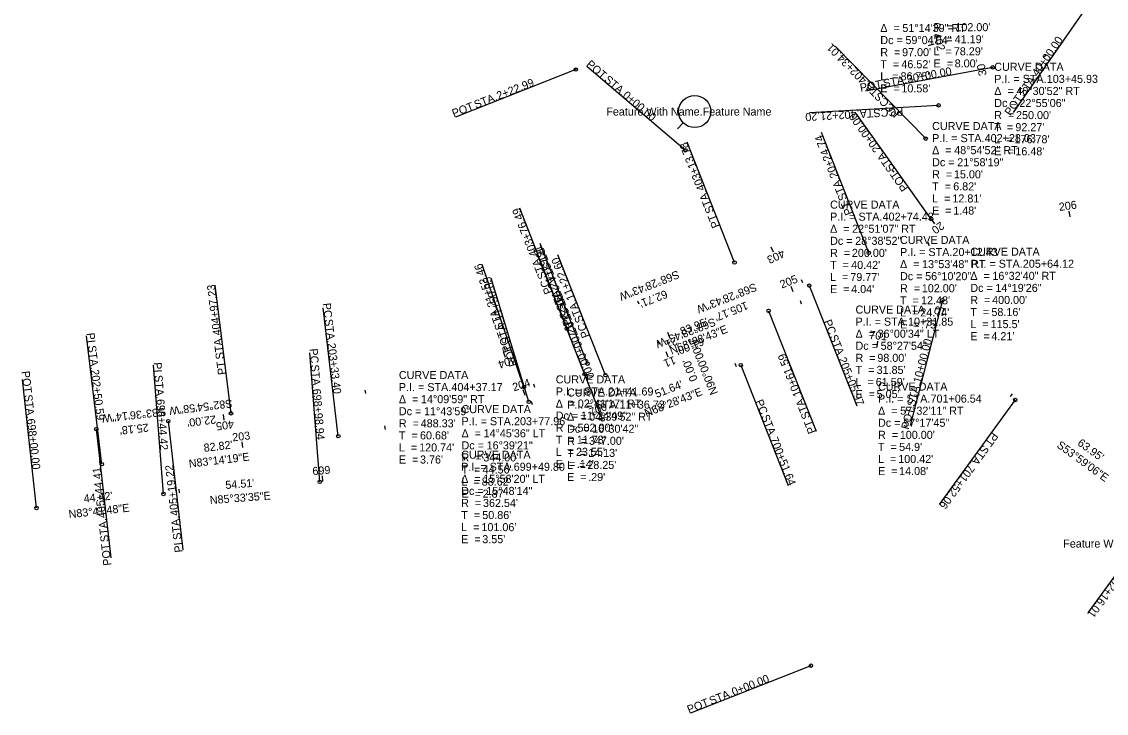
# Model space of a CAD drawing. Extents: x 1600023 to 1602131, y 285824 to 287284.
# Drawn here: x 1600627.4 to 1601004.6, y 286516.7 to 286757.4 of the extents above; entities that cross this region are included whole.
import ezdxf

# ---------------------------------------------------------------- set-up
doc = ezdxf.new("R2010")
doc.units = 0
for name, color, linetype in [('_CIVIL_CONSTRUCTION', 7, 'Continuous'), ('Default', 7, 'Continuous'), ('GE_P_Alignment', 7, 'Continuous'), ('PF_P_Grade_Line', 7, 'Continuous'), ('PF_X_Ground_Line', 7, 'Continuous'), ('PV_P_Curb', 7, 'Continuous'), ('SC_Scratch6', 7, 'Continuous'), ('SC_Scratch8', 7, 'Continuous')]:
    doc.layers.add(name, color=color, linetype=linetype)

msp = doc.modelspace()

# ---------------------------------------------------------------- linework, layer by layer
at = {"layer": '_CIVIL_CONSTRUCTION'}
for p, q in [((1600820.1, 286740.73), (1600778.24, 286724.22)), ((1600858.21, 286712.63), (1600823.92, 286741.77)), ((1600823.21, 286634.77), (1600806.71, 286676.63)), ((1600901.31, 286665.57), (1600917.82, 286623.7)), ((1600737.52, 286613.18), (1600732.22, 286657.87)), ((1600655.28, 286603.43), (1600649.98, 286648.12)), ((1600901.9, 286533.29), (1600860.04, 286516.78))]:
    msp.add_line(p, q, dxfattribs=at)
for centre in [(1600820.1, 286740.73), (1600858.21, 286712.63), (1600901.31, 286665.57), (1600823.21, 286634.77), (1600737.52, 286613.18), (1600655.28, 286603.43), (1600901.9, 286533.29)]:
    msp.add_circle(centre, 0.6, dxfattribs=at)
at = {"layer": 'Default'}
for p, q in [((1600997.93, 286762.76), (1600972.29, 286725.78)), ((1600941.81, 286716.69), (1600910.34, 286748.85)), ((1600942.79, 286749.14), (1600944.71, 286749.68)), ((1600965.11, 286741.49), (1600920.87, 286733.24)), ((1600965.11, 286741.49), (1600963.14, 286741.12)), ((1600946.3, 286728.27), (1600901.37, 286725.69)), ((1600943.72, 286688.73), (1600917.64, 286725.4)), ((1600922.03, 286676.96), (1600905.52, 286718.82)), ((1600875.32, 286673.59), (1600858.81, 286715.45)), ((1600929.95, 286705.97), (1600930.72, 286705.05)), ((1600816.98, 286650.58), (1600800.67, 286692.52)), ((1600943.72, 286688.73), (1600944.88, 286687.1)), ((1600824.19, 286638.38), (1600807.68, 286680.24)), ((1600887.95, 286679.08), (1600888.81, 286677.28)), ((1600802.08, 286630.26), (1600787.56, 286672.85)), ((1600830.42, 286634.39), (1600813.91, 286676.25)), ((1600700.21, 286621.1), (1600694.66, 286665.76)), ((1600803.75, 286625.1), (1600790.7, 286668.17)), ((1600898.53, 286667.69), (1600898.97, 286666.58)), ((1600829.45, 286618.95), (1600812.94, 286660.82)), ((1600841.62, 286660.3), (1600842.06, 286659.19)), ((1600898.18, 286660.37), (1600898.49, 286659.21)), ((1600947.64, 286660.48), (1600936.38, 286616.91)), ((1600947.64, 286660.48), (1600947.14, 286658.55)), ((1600887.17, 286656.77), (1600903.68, 286614.9)), ((1600852.02, 286649.35), (1600852.75, 286647.49)), ((1600924.95, 286644.29), (1600925.17, 286646.27)), ((1600794.87, 286642.59), (1600795.5, 286640.7)), ((1600851.44, 286642.68), (1600852.18, 286640.82)), ((1600731.07, 286597.28), (1600727.59, 286642.14)), ((1600676.73, 286593.06), (1600673.24, 286637.92)), ((1600875.97, 286637.3), (1600875.52, 286638.41)), ((1600877.49, 286637.9), (1600893.99, 286596.03)), ((1600632.57, 286588.18), (1600627.63, 286632.91)), ((1600805.36, 286631.39), (1600805.75, 286630.25)), ((1600746.72, 286629.19), (1600746.98, 286628.01)), ((1600971.3, 286626.95), (1600971.98, 286627.93)), ((1600804.56, 286625.35), (1600804.91, 286624.2)), ((1600972.97, 286625.76), (1600946.51, 286589.36)), ((1600697.46, 286620.76), (1600697.7, 286618.78)), ((1600829.45, 286618.95), (1600828.72, 286620.82)), ((1600678.38, 286618.39), (1600683.4, 286573.67)), ((1600653.36, 286615.59), (1600658.37, 286570.87)), ((1600781.54, 286604.8), (1600781.28, 286605.97)), ((1600732.13, 286597.36), (1600731.97, 286599.36)), ((1600682.28, 286593.49), (1600682.19, 286594.69)), ((1601024.7, 286588.15), (1600998.24, 286551.75))]:
    msp.add_line(p, q, dxfattribs=at)
for centre in [(1600965.11, 286741.49), (1600946.3, 286728.27), (1600941.81, 286716.69), (1600943.72, 286688.73), (1600922.03, 286676.96), (1600875.32, 286673.59), (1600947.64, 286660.48), (1600887.17, 286656.77), (1600816.98, 286650.58), (1600824.19, 286638.38), (1600830.42, 286634.39), (1600877.49, 286637.9), (1600802.08, 286630.26), (1600803.75, 286625.1), (1600972.97, 286625.76), (1600700.21, 286621.1), (1600653.36, 286615.59), (1600678.38, 286618.39), (1600829.45, 286618.95), (1600731.07, 286597.28), (1600676.73, 286593.06), (1600632.57, 286588.18)]:
    msp.add_circle(centre, 0.6, dxfattribs=at)
at = {"layer": 'PV_P_Curb'}
msp.add_circle((1600861.48, 286726.12), 5.6, dxfattribs=at)
at = {"layer": 'SC_Scratch6'}
for p, q in [((1600982.8, 286745.17), (1600983.82, 286745.81)), ((1600992.02, 286689.51), (1600991.74, 286691.49)), ((1600943.08, 286679.43), (1600942.76, 286680.59)), ((1600895.76, 286663.38), (1600895.03, 286665.24)), ((1600849.25, 286645.03), (1600848.8, 286646.15)), ((1600802.49, 286627.35), (1600801.87, 286629.26)), ((1600753.95, 286615.53), (1600753.75, 286616.71)), ((1600704.35, 286609.25), (1600704.12, 286611.23)), ((1600654.7, 286603.36), (1600654.57, 286604.56))]:
    msp.add_line(p, q, dxfattribs=at)
at = {"layer": 'SC_Scratch8'}
msp.add_line((1600855.48, 286720.12), (1600857.52, 286722.16), dxfattribs=at)
msp.add_lwpolyline([(1600855.48, 286720.12), (1600856.19, 286720.83), (1600856.19, 286720.83)], close=True, dxfattribs=at)

# ---------------------------------------------------------------- texts
at = {"layer": '_CIVIL_CONSTRUCTION'}
for s, rotation, p in [('POT', 319.6453, (1600823.51, 286742.17)), ('2+22.99', 21.5214, (1600793.22, 286730.17)), (' STA. ', 319.6453, (1600829, 286737.51)), ('0+00.00', 319.6453, (1600836.2, 286731.39)), ('POT', 21.5214, (1600777.72, 286724.07)), (' STA. ', 21.5214, (1600784.42, 286726.71)), ('PT', 291.5214, (1600806.25, 286677.89)), (' STA. ', 291.5214, (1600807.87, 286673.79)), ('204+22.02', 291.5214, (1600811.34, 286664.99)), ('PC', 276.7614, (1600732.09, 286659.35)), (' STA. ', 276.7614, (1600732.63, 286654.8)), ('PC', 291.5214, (1600906.28, 286653.08)), ('PI', 276.7614, (1600649.92, 286648.98)), (' STA. ', 291.5214, (1600907.96, 286648.81)), (' STA. ', 276.7614, (1600650.32, 286645.61)), ('203+33.40', 276.7614, (1600733.74, 286645.41)), ('205+05.97', 291.5214, (1600911.43, 286640.02)), ('202+50.59', 276.7614, (1600651.43, 286636.23)), ('0+00.00', 21.5214, (1600874.99, 286522.73)), ('POT', 21.5214, (1600859.5, 286516.62)), (' STA. ', 21.5214, (1600866.2, 286519.26))]:
    msp.add_text(s, height=2.8, rotation=rotation, dxfattribs=at).set_placement(p)
at = {"layer": 'Default'}
for s, p in [('Δ  = ', (1600926.02, 286753.79)), ('51°14\'39" RT', (1600933.7, 286753.79)), ('R  = ', (1600944.56, 286754.08)), ("102.00'", (1600952.14, 286754.08)), ('Dc = ', (1600926.02, 286749.59)), ('59°04\'04"', (1600934.76, 286749.59)), ('T  = ', (1600944.56, 286749.88)), ("41.19'", (1600951.9, 286749.88)), ('R  = ', (1600926.02, 286745.39)), ("97.00'", (1600933.6, 286745.39)), ('L  = ', (1600944.56, 286745.68)), ("78.29'", (1600951.6, 286745.68)), ('E  = ', (1600944.56, 286741.48)), ("8.00'", (1600951.9, 286741.48)), ('T  = ', (1600926.02, 286741.19)), ("46.52'", (1600933.36, 286741.19)), ('L  = ', (1600926.02, 286736.99)), ("86.75'", (1600933.06, 286736.99)), ('E  = ', (1600926.02, 286732.79)), ("10.58'", (1600933.36, 286732.79)), ('CURVE DATA', (1600944.05, 286719.68)), ('P.I. = STA. ', (1600944.05, 286715.48)), ('402+28.03', (1600962.32, 286715.48)), ('48°54\'52" RT', (1600951.73, 286711.28)), ('Δ  = ', (1600944.05, 286711.28)), ('Dc = ', (1600944.05, 286707.08)), ('21°58\'19"', (1600952.79, 286707.08)), ('R  = ', (1600944.05, 286702.88)), ("15.00'", (1600951.64, 286702.88)), ('T  = ', (1600944.05, 286698.68)), ("6.82'", (1600951.39, 286698.68)), ('L  = ', (1600944.05, 286694.48)), ("12.81'", (1600951.1, 286694.48)), ('CURVE DATA', (1600908.56, 286692.34)), ('E  = ', (1600944.05, 286690.28)), ("1.48'", (1600951.39, 286690.28)), ('P.I. = STA. ', (1600908.56, 286688.14)), ('402+74.43', (1600926.83, 286688.14)), ('Δ  = ', (1600908.56, 286683.94)), ('22°51\'07" RT', (1600916.24, 286683.94)), ('Dc = ', (1600908.56, 286679.74)), ('28°38\'52"', (1600917.3, 286679.74)), ('CURVE DATA', (1600932.88, 286680.04)), ('R  = ', (1600908.56, 286675.54)), ("200.00'", (1600916.15, 286675.54)), ('P.I. = STA. ', (1600932.88, 286675.84)), ('20+12.43', (1600951.14, 286675.84)), ('T  = ', (1600908.56, 286671.34)), ("40.42'", (1600915.9, 286671.34)), ('Δ  = ', (1600932.88, 286671.64)), ('13°53\'48" RT', (1600940.55, 286671.64)), ('L  = ', (1600908.56, 286667.14)), ("79.77'", (1600915.6, 286667.14)), ('Dc = ', (1600932.88, 286667.44)), ('56°10\'20"', (1600941.62, 286667.44)), ('E  = ', (1600908.56, 286662.94)), ("4.04'", (1600915.9, 286662.94)), ('R  = ', (1600932.88, 286663.24)), ("102.00'", (1600940.46, 286663.24)), ('T  = ', (1600932.88, 286659.04)), ("12.43'", (1600940.21, 286659.04)), ('CURVE DATA', (1600917.41, 286655.82)), ('L  = ', (1600932.88, 286654.84)), ("24.74'", (1600939.92, 286654.84)), ('P.I. = STA. ', (1600917.41, 286651.62)), ('10+31.85', (1600935.67, 286651.62)), ('Δ  = ', (1600917.41, 286647.42)), ('36°00\'34" LT', (1600925.08, 286647.42)), ('E  = ', (1600932.88, 286650.64)), (".75'", (1600940.22, 286650.64)), ('Dc = ', (1600917.41, 286643.22)), ('58°27\'54"', (1600926.15, 286643.22)), ('R  = ', (1600917.41, 286639.02)), ("98.00'", (1600924.99, 286639.02)), ('CURVE DATA', (1600758.59, 286633.04)), ('T  = ', (1600917.41, 286634.82)), ("31.85'", (1600924.75, 286634.82)), ('P.I. = STA. ', (1600758.59, 286628.84)), ('404+37.17', (1600776.86, 286628.84)), ('CURVE DATA', (1600813.14, 286631.52)), ('L  = ', (1600917.41, 286630.62)), ("61.59'", (1600924.45, 286630.62)), ('CURVE DATA', (1600925.23, 286629.03)), ('Δ  = ', (1600758.59, 286624.64)), ('14°09\'59" RT', (1600766.27, 286624.64)), ('P.I. = STA. ', (1600813.14, 286627.32)), ('CURVE DATA', (1600817.09, 286626.95)), ('21+41.69', (1600831.4, 286627.32)), ('E  = ', (1600917.41, 286626.42)), ("5.05'", (1600924.75, 286626.42)), ('P.I. = STA. ', (1600925.23, 286624.83)), ('701+06.54', (1600943.5, 286624.83)), ('Δ  = ', (1600813.14, 286623.12)), ('P.I. = STA. ', (1600817.09, 286622.75)), ('02°41\'17" RT', (1600820.81, 286623.12)), ('11+36.73', (1600835.35, 286622.75)), ('Dc = ', (1600758.59, 286620.44)), ('11°43\'59"', (1600767.33, 286620.44)), ('Dc = ', (1600813.14, 286618.92)), ('Δ  = ', (1600817.09, 286618.55)), ('11°24\'49"', (1600821.88, 286618.92)), ('04°39\'52" RT', (1600824.76, 286618.55)), ('Δ  = ', (1600925.23, 286620.63)), ('57°32\'11" RT', (1600932.91, 286620.63)), ('R  = ', (1600758.59, 286616.24)), ("488.33'", (1600766.18, 286616.24)), ('R  = ', (1600813.14, 286614.72)), ('Dc = ', (1600817.09, 286614.35)), ("502.00'", (1600820.72, 286614.72)), ('16°30\'42"', (1600825.82, 286614.35)), ('Dc = ', (1600925.23, 286616.43)), ('57°17\'45"', (1600933.97, 286616.43)), ('T  = ', (1600758.59, 286612.04)), ("60.68'", (1600765.93, 286612.04)), ('T  = ', (1600813.14, 286610.52)), ('R  = ', (1600817.09, 286610.15)), ("11.78'", (1600820.47, 286610.52)), ("347.00'", (1600824.67, 286610.15)), ('R  = ', (1600925.23, 286612.23)), ("100.00'", (1600932.81, 286612.23)), ('L  = ', (1600758.59, 286607.84)), ("120.74'", (1600765.64, 286607.84)), ('L  = ', (1600813.14, 286606.32)), ('T  = ', (1600817.09, 286605.95)), ("23.55'", (1600820.18, 286606.32)), ("14.13'", (1600824.42, 286605.95)), ('T  = ', (1600925.23, 286608.03)), ("54.9'", (1600932.57, 286608.03)), ('E  = ', (1600758.59, 286603.64)), ("3.76'", (1600765.94, 286603.64)), ('CURVE DATA', (1600780.26, 286605.32)), ('E  = ', (1600813.14, 286602.12)), (".14'", (1600820.48, 286602.12)), ('L  = ', (1600925.23, 286603.83)), ("100.42'", (1600932.27, 286603.83)), ('P.I. = STA. ', (1600780.26, 286601.12)), ('699+49.80', (1600798.53, 286601.12)), ('L  = ', (1600817.09, 286601.75)), ("28.25'", (1600824.13, 286601.75)), ('E  = ', (1600925.23, 286599.63)), ("14.08'", (1600932.57, 286599.63)), ('Δ  = ', (1600780.26, 286596.92)), ('15°58\'20" LT', (1600787.94, 286596.92)), ('E  = ', (1600817.09, 286597.55)), (".29'", (1600824.43, 286597.55)), ('Dc = ', (1600780.26, 286592.72)), ('15°48\'14"', (1600789, 286592.72)), ('R  = ', (1600780.26, 286588.52)), ("362.54'", (1600787.84, 286588.52)), ('T  = ', (1600780.26, 286584.32)), ("50.86'", (1600787.6, 286584.32)), ('L  = ', (1600780.26, 286580.12)), ("101.06'", (1600787.3, 286580.12)), ('E  = ', (1600780.26, 286575.92)), ("3.55'", (1600787.6, 286575.92))]:
    msp.add_text(s, height=2.8, dxfattribs=at).set_placement(p)
for s, rotation, p in [('402', 285.8126, (1600944.3, 286752.97)), ('40+00.00', 55.2657, (1600980.79, 286738.11)), ('402+34.01', 134.3733, (1600921.57, 286737.31)), ('30+00.00', 10.5564, (1600935.58, 286736.03)), ('30', 100.5564, (1600963.06, 286738.84)), ('POT', 10.5564, (1600919.21, 286732.98)), (' STA. ', 134.3733, (1600928.18, 286730.55)), (' STA. ', 10.5564, (1600926.29, 286734.3)), (' STA. ', 55.2657, (1600975.4, 286730.34)), ('PCC', 134.3733, (1600933, 286725.63)), ('POT', 55.2657, (1600971.3, 286724.42)), ('402+21.20', 183.2876, (1600917.65, 286726.58)), ('20+00.00', 125.418, (1600926.32, 286713.13)), (' STA. ', 183.2876, (1600927.08, 286727.12)), ('PCC', 183.2876, (1600933.96, 286727.52)), ('20+24.74', 111.5214, (1600911.48, 286703.6)), ('403+13.78', 111.5214, (1600865.2, 286699.13)), (' STA. ', 125.418, (1600931.8, 286705.42)), (' STA. ', 111.5214, (1600914.95, 286694.81)), ('POT', 125.418, (1600935.97, 286699.55)), (' STA. ', 111.5214, (1600868.67, 286690.34)), ('403+76.49', 111.2524, (1600806.94, 286676.27)), ('PT', 111.5214, (1600916.57, 286690.7)), ('PT', 111.5214, (1600870.28, 286686.23)), ('20', 215.418, (1600946.99, 286687.98)), ('21+29.91', 111.5214, (1600813.56, 286665.21)), ('403', 205.4686, (1600891.98, 286678.23)), ('21+53.46', 108.8333, (1600792.37, 286658.6)), (' STA. ', 111.2524, (1600810.37, 286667.46)), ('11+22.60', 111.5214, (1600819.87, 286661.04)), ('S68°28\'43"W', 201.5214, (1600855.45, 286670.91)), ('404+97.23', 97.0838, (1600696.77, 286648.42)), ('11+50.85', 106.8568, (1600795.01, 286653.82)), ('PC', 111.2524, (1600812.03, 286663.19)), ('S68°28\'43"W', 201.5214, (1600882.41, 286666.5)), (' STA. ', 111.5214, (1600817.03, 286656.42)), ('PT', 291.5214, (1600812.47, 286662.14)), ("62.71'", 201.5214, (1600851.34, 286664.09)), (' STA. ', 108.8333, (1600795.42, 286649.65)), (' STA. ', 291.5214, (1600814.09, 286658.03)), (' STA. ', 111.5214, (1600823.34, 286652.24)), ("105.17'", 201.5214, (1600879.34, 286660.08)), ('10', 165.5121, (1600949.18, 286657.5)), ('PC', 111.5214, (1600818.71, 286652.15)), ('S68°28\'43"W', 201.5214, (1600868.1, 286654.4)), (' STA. ', 106.8568, (1600797.75, 286644.77)), ('700+00.00', 291.5214, (1600817.55, 286649.24)), ('PC', 111.5214, (1600825.02, 286647.98)), (' STA. ', 97.0838, (1600697.94, 286639.04)), ('POT', 108.8333, (1600797.75, 286642.84)), ('21', 201.5214, (1600854.82, 286647.77)), ("61.00'", 201.5214, (1600863.99, 286647.58)), ('701', 353.8105, (1600922.09, 286647.11)), ('10+00.00', 75.5121, (1600940.09, 286631.42)), ('PC', 274.4402, (1600727.52, 286643.56)), ('POT', 106.8568, (1600799.83, 286637.88)), ('PI', 274.4402, (1600673.22, 286638.75)), ('PT', 97.0838, (1600698.48, 286634.66)), ('404', 198.4937, (1600798.76, 286641.26)), ('11', 201.5214, (1600854.25, 286641.1)), ('10+61.59', 111.5214, (1600898.65, 286627.55)), ('POT', 276.3033, (1600627.37, 286635.7)), (' STA. ', 274.4402, (1600727.88, 286638.99)), (' STA. ', 274.4402, (1600673.48, 286635.37)), ("51.64'", 21.5214, (1600848.28, 286626.42)), (' STA. ', 75.5121, (1600937.72, 286622.27)), (' STA. ', 276.3033, (1600628.16, 286628.54)), ('698+98.94', 274.4402, (1600728.61, 286629.56)), ('N68°28\'43"E', 21.5214, (1600844.66, 286619.79)), ('698+44.42', 274.4402, (1600674.21, 286625.95)), ('S82°54\'58"W', 187.0838, (1600700.5, 286625.98)), ('700', 21.5214, (1600825.42, 286620.05)), ('PC', 291.5214, (1600882.51, 286625.28)), (' STA. ', 111.5214, (1600902.12, 286618.75)), ('S83°36\'14"W', 186.3962, (1600677.15, 286623.08)), ("22.00'", 187.0838, (1600694.82, 286620.39)), (' STA. ', 291.5214, (1600884.19, 286621.01)), ('POT', 75.5121, (1600935.92, 286615.3)), ('698+00.00', 276.3033, (1600629.2, 286619.14)), ("25.18'", 186.3962, (1600671.4, 286617.57)), ('405', 187.0838, (1600701.05, 286618.69)), ('PT', 111.5214, (1600903.74, 286614.65)), ('700+51.64', 291.5214, (1600887.66, 286612.22)), ('PT', 233.985, (1600965.02, 286614.74)), (' STA. ', 233.985, (1600962.42, 286611.17)), ('S53°59\'06"E', 323.985, (1600987.16, 286609.5)), ("63.95'", 323.985, (1600994.36, 286610.26)), ('405+44.41', 96.3962, (1600656.76, 286584.82)), ('405+19.22', 96.3962, (1600682.02, 286585.61)), ('699', 4.6084, (1600728.63, 286599.59)), ('701+52.06', 233.985, (1600956.87, 286603.53)), ("54.51'", 4.4402, (1600698.35, 286594.78)), ("44.42'", 6.3033, (1600649.12, 286590.03)), ('N85°33\'35"E', 4.4402, (1600692.94, 286589.5)), ('N83°41\'48"E', 6.3033, (1600643.88, 286584.6)), (' STA. ', 96.3962, (1600657.82, 286575.43)), (' STA. ', 96.3962, (1600683.07, 286576.22)), ('POT', 96.3962, (1600658.62, 286568.27)), ('PI', 96.3962, (1600683.45, 286572.85)), ('702+16.01', 233.985, (1601008.42, 286565.69))]:
    msp.add_text(s, height=2.8, rotation=rotation, dxfattribs=at).set_placement(p)
at = {"layer": 'GE_P_Alignment'}
for s, rotation, p in [('N68°28\'43"E', 21.5214, (1600853.45, 286641.53)), ('N90°00\'00"E', 111.5214, (1600869.64, 286628.2)), ('N83°14\'19"E', 6.7614, (1600685.68, 286602.2))]:
    msp.add_text(s, height=2.8, rotation=rotation, dxfattribs=at).set_placement(p)
at = {"layer": 'PF_P_Grade_Line'}
for s, rotation, p in [("83.95'", 21.5214, (1600857.07, 286648.17)), ("0.00'", 111.5214, (1600862.59, 286632.86)), ("82.82'", 6.7614, (1600690.87, 286607.69))]:
    msp.add_text(s, height=2.8, rotation=rotation, dxfattribs=at).set_placement(p)
at = {"layer": 'PF_X_Ground_Line'}
for s, p in [('CURVE DATA', (1600965.66, 286740.29)), ('P.I. = STA. ', (1600965.66, 286736.09)), ('103+45.93', (1600983.93, 286736.09)), ('Δ  = ', (1600965.66, 286731.89)), ('40°30\'52" RT', (1600973.34, 286731.89)), ('Dc = ', (1600965.66, 286727.69)), ('22°55\'06"', (1600974.4, 286727.69)), ('R  = ', (1600965.66, 286723.49)), ("250.00'", (1600973.24, 286723.49)), ('T  = ', (1600965.66, 286719.29)), ("92.27'", (1600973, 286719.29)), ('L  = ', (1600965.66, 286715.09)), ("176.78'", (1600972.7, 286715.09)), ('E  = ', (1600965.66, 286710.89)), ("16.48'", (1600973, 286710.89)), ('CURVE DATA', (1600957.33, 286675.96)), ('P.I. = STA. ', (1600957.33, 286671.76)), ('205+64.12', (1600975.6, 286671.76)), ('Δ  = ', (1600957.33, 286667.56)), ('16°32\'40" RT', (1600965.01, 286667.56)), ('Dc = ', (1600957.33, 286663.36)), ('14°19\'26"', (1600966.07, 286663.36)), ('R  = ', (1600957.33, 286659.16)), ("400.00'", (1600964.91, 286659.16)), ('T  = ', (1600957.33, 286654.96)), ("58.16'", (1600964.67, 286654.96)), ('L  = ', (1600957.33, 286650.76)), ("115.5'", (1600964.37, 286650.76)), ('E  = ', (1600957.33, 286646.56)), ("4.21'", (1600964.67, 286646.56)), ('CURVE DATA', (1600780.37, 286621.17)), ('P.I. = STA. ', (1600780.37, 286616.97)), ('203+77.96', (1600798.63, 286616.97)), ('Δ  = ', (1600780.37, 286612.77)), ('14°45\'36" LT', (1600788.04, 286612.77)), ('Dc = ', (1600780.37, 286608.57)), ('16°39\'21"', (1600789.11, 286608.57)), ('R  = ', (1600780.37, 286604.37)), ("344.00'", (1600787.95, 286604.37)), ('T  = ', (1600780.37, 286600.17)), ("44.56'", (1600787.7, 286600.17)), ('L  = ', (1600780.37, 286595.97)), ("88.62'", (1600787.41, 286595.97)), ('E  = ', (1600780.37, 286591.77)), ("2.87'", (1600787.71, 286591.77))]:
    msp.add_text(s, height=2.8, dxfattribs=at).set_placement(p)
at = {"layer": 'PV_P_Curb'}
for p in [(1600830.73, 286724.72), (1600989.65, 286574.4)]:
    msp.add_text('Feature With Name.Feature Name', height=2.8, dxfattribs=at).set_placement(p)
at = {"layer": 'SC_Scratch6'}
for s, rotation, p in [('206', 8.0525, (1600988.34, 286691.52)), ('205', 21.5214, (1600891.77, 286664.49)), ('204', 17.854, (1600798.61, 286628.73)), ('203', 6.7614, (1600700.81, 286611.34))]:
    msp.add_text(s, height=2.8, rotation=rotation, dxfattribs=at).set_placement(p)

doc.saveas('drawing.dxf')
